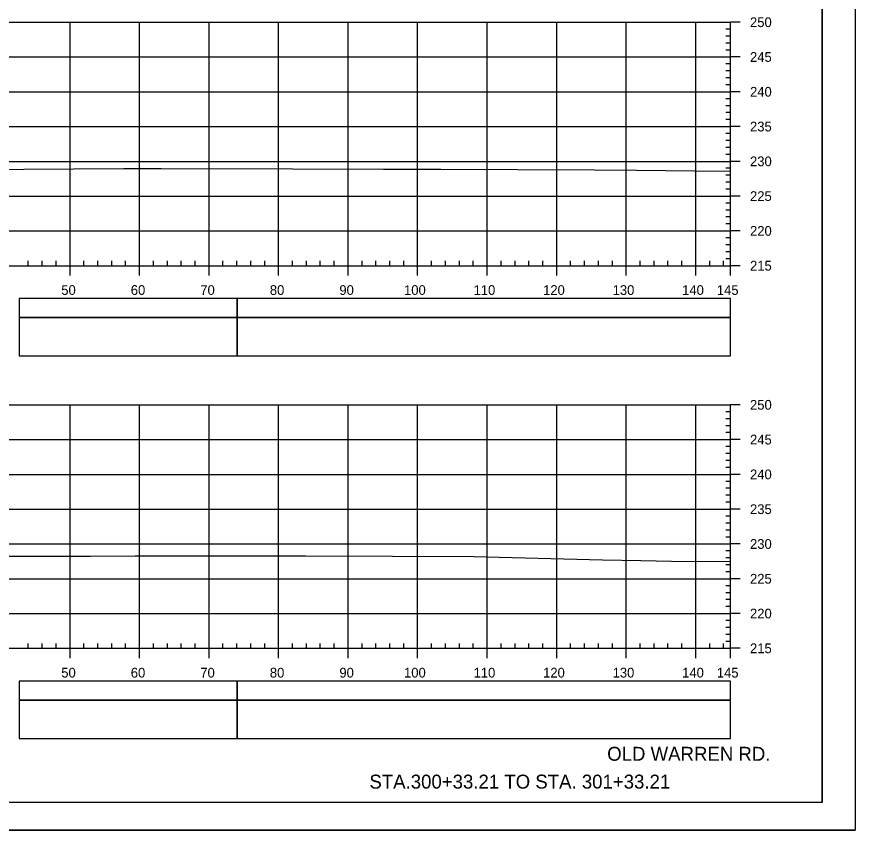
# Model space of a CAD drawing. Extents: x 1386544 to 1388153, y 379785 to 390999.
# Drawn here: x 1386757.2 to 1386877.8, y 384065.3 to 384182.2 of the extents above; entities that cross this region are included whole.
import ezdxf

# ---------------------------------------------------------------- set-up
doc = ezdxf.new("R2010")
doc.units = 0
for name, color, linetype in [('R_Axis', 7, 'Continuous'), ('R_Axis Annot', 7, 'Continuous'), ('R_Border', 7, 'Continuous'), ('R_Draft', 7, 'Continuous'), ('R_Exist Surface', 7, 'Continuous'), ('R_Grid', 7, 'Continuous'), ('R_No Plot', 7, 'Continuous'), ('R_Striping', 7, 'Continuous')]:
    doc.layers.add(name, color=color, linetype=linetype)

msp = doc.modelspace()

# ---------------------------------------------------------------- linework, layer by layer
at = {"layer": 'R_Axis'}
for p, q in [((1386859.87, 384146.41), (1386859.87, 384181.41)), ((1386861.27, 384181.41), (1386859.87, 384181.41)), ((1386859.87, 384180.41), (1386859.17, 384180.41)), ((1386859.87, 384179.41), (1386859.17, 384179.41)), ((1386859.87, 384178.41), (1386859.17, 384178.41)), ((1386859.87, 384177.41), (1386859.17, 384177.41)), ((1386861.27, 384176.41), (1386859.87, 384176.41)), ((1386859.87, 384175.41), (1386859.17, 384175.41)), ((1386859.87, 384174.41), (1386859.17, 384174.41)), ((1386859.87, 384173.41), (1386859.17, 384173.41)), ((1386859.87, 384172.41), (1386859.17, 384172.41)), ((1386861.27, 384171.41), (1386859.87, 384171.41)), ((1386859.87, 384170.41), (1386859.17, 384170.41)), ((1386859.87, 384169.41), (1386859.17, 384169.41)), ((1386859.87, 384168.41), (1386859.17, 384168.41)), ((1386859.87, 384167.41), (1386859.17, 384167.41)), ((1386859.87, 384165.41), (1386859.17, 384165.41)), ((1386861.27, 384166.41), (1386859.87, 384166.41)), ((1386859.87, 384164.41), (1386859.17, 384164.41)), ((1386859.87, 384163.41), (1386859.17, 384163.41)), ((1386859.87, 384162.41), (1386859.17, 384162.41)), ((1386861.27, 384161.41), (1386859.87, 384161.41)), ((1386859.87, 384160.41), (1386859.17, 384160.41)), ((1386859.87, 384159.41), (1386859.17, 384159.41)), ((1386859.87, 384158.41), (1386859.17, 384158.41)), ((1386859.87, 384157.41), (1386859.17, 384157.41)), ((1386861.27, 384156.41), (1386859.87, 384156.41)), ((1386859.87, 384155.41), (1386859.17, 384155.41)), ((1386859.87, 384154.41), (1386859.17, 384154.41)), ((1386859.87, 384153.41), (1386859.17, 384153.41)), ((1386859.87, 384152.41), (1386859.17, 384152.41)), ((1386861.27, 384151.41), (1386859.87, 384151.41)), ((1386859.87, 384150.41), (1386859.17, 384150.41)), ((1386859.87, 384149.41), (1386859.17, 384149.41)), ((1386859.87, 384148.41), (1386859.17, 384148.41)), ((1386859.87, 384147.41), (1386859.17, 384147.41)), ((1386569.87, 384146.41), (1386859.87, 384146.41)), ((1386758.87, 384146.41), (1386758.87, 384147.11)), ((1386760.87, 384146.41), (1386760.87, 384147.11)), ((1386762.87, 384146.41), (1386762.87, 384147.11)), ((1386764.87, 384145.01), (1386764.87, 384146.41)), ((1386766.87, 384146.41), (1386766.87, 384147.11)), ((1386768.87, 384146.41), (1386768.87, 384147.11)), ((1386770.87, 384146.41), (1386770.87, 384147.11)), ((1386772.87, 384146.41), (1386772.87, 384147.11)), ((1386774.87, 384145.01), (1386774.87, 384146.41)), ((1386776.87, 384146.41), (1386776.87, 384147.11)), ((1386778.87, 384146.41), (1386778.87, 384147.11)), ((1386780.87, 384146.41), (1386780.87, 384147.11)), ((1386782.87, 384146.41), (1386782.87, 384147.11)), ((1386784.87, 384145.01), (1386784.87, 384146.41)), ((1386786.87, 384146.41), (1386786.87, 384147.11)), ((1386788.87, 384146.41), (1386788.87, 384147.11)), ((1386790.87, 384146.41), (1386790.87, 384147.11)), ((1386792.87, 384146.41), (1386792.87, 384147.11)), ((1386794.87, 384145.01), (1386794.87, 384146.41)), ((1386796.87, 384146.41), (1386796.87, 384147.11)), ((1386798.87, 384146.41), (1386798.87, 384147.11)), ((1386800.87, 384146.41), (1386800.87, 384147.11)), ((1386802.87, 384146.41), (1386802.87, 384147.11)), ((1386804.87, 384145.01), (1386804.87, 384146.41)), ((1386806.87, 384146.41), (1386806.87, 384147.11)), ((1386808.87, 384146.41), (1386808.87, 384147.11)), ((1386810.87, 384146.41), (1386810.87, 384147.11)), ((1386812.87, 384146.41), (1386812.87, 384147.11)), ((1386814.87, 384145.01), (1386814.87, 384146.41)), ((1386816.87, 384146.41), (1386816.87, 384147.11)), ((1386818.87, 384146.41), (1386818.87, 384147.11)), ((1386820.87, 384146.41), (1386820.87, 384147.11)), ((1386822.87, 384146.41), (1386822.87, 384147.11)), ((1386824.87, 384145.01), (1386824.87, 384146.41)), ((1386826.87, 384146.41), (1386826.87, 384147.11)), ((1386828.87, 384146.41), (1386828.87, 384147.11)), ((1386830.87, 384146.41), (1386830.87, 384147.11)), ((1386832.87, 384146.41), (1386832.87, 384147.11)), ((1386834.87, 384145.01), (1386834.87, 384146.41)), ((1386836.87, 384146.41), (1386836.87, 384147.11)), ((1386838.87, 384146.41), (1386838.87, 384147.11)), ((1386840.87, 384146.41), (1386840.87, 384147.11)), ((1386842.87, 384146.41), (1386842.87, 384147.11)), ((1386844.87, 384145.01), (1386844.87, 384146.41)), ((1386846.87, 384146.41), (1386846.87, 384147.11)), ((1386848.87, 384146.41), (1386848.87, 384147.11)), ((1386850.87, 384146.41), (1386850.87, 384147.11)), ((1386852.87, 384146.41), (1386852.87, 384147.11)), ((1386854.87, 384145.01), (1386854.87, 384146.41)), ((1386856.87, 384146.41), (1386856.87, 384147.11)), ((1386858.87, 384146.41), (1386858.87, 384147.11)), ((1386859.87, 384145.01), (1386859.87, 384146.41)), ((1386861.27, 384146.41), (1386859.87, 384146.41)), ((1386859.87, 384091.41), (1386859.87, 384126.41)), ((1386861.27, 384126.41), (1386859.87, 384126.41)), ((1386859.87, 384125.41), (1386859.17, 384125.41)), ((1386859.87, 384124.41), (1386859.17, 384124.41)), ((1386859.87, 384123.41), (1386859.17, 384123.41)), ((1386859.87, 384122.41), (1386859.17, 384122.41)), ((1386861.27, 384121.41), (1386859.87, 384121.41)), ((1386859.87, 384120.41), (1386859.17, 384120.41)), ((1386859.87, 384119.41), (1386859.17, 384119.41)), ((1386859.87, 384118.41), (1386859.17, 384118.41)), ((1386859.87, 384117.41), (1386859.17, 384117.41)), ((1386861.27, 384116.41), (1386859.87, 384116.41)), ((1386859.87, 384115.41), (1386859.17, 384115.41)), ((1386859.87, 384114.41), (1386859.17, 384114.41)), ((1386859.87, 384113.41), (1386859.17, 384113.41)), ((1386859.87, 384112.41), (1386859.17, 384112.41)), ((1386861.27, 384111.41), (1386859.87, 384111.41)), ((1386859.87, 384110.41), (1386859.17, 384110.41)), ((1386859.87, 384109.41), (1386859.17, 384109.41)), ((1386859.87, 384108.41), (1386859.17, 384108.41)), ((1386859.87, 384107.41), (1386859.17, 384107.41)), ((1386861.27, 384106.41), (1386859.87, 384106.41)), ((1386859.87, 384105.41), (1386859.17, 384105.41)), ((1386859.87, 384104.41), (1386859.17, 384104.41)), ((1386859.87, 384103.41), (1386859.17, 384103.41)), ((1386859.87, 384102.41), (1386859.17, 384102.41)), ((1386859.87, 384100.41), (1386859.17, 384100.41)), ((1386861.27, 384101.41), (1386859.87, 384101.41)), ((1386859.87, 384099.41), (1386859.17, 384099.41)), ((1386859.87, 384098.41), (1386859.17, 384098.41)), ((1386859.87, 384097.41), (1386859.17, 384097.41)), ((1386859.87, 384095.41), (1386859.17, 384095.41)), ((1386861.27, 384096.41), (1386859.87, 384096.41)), ((1386859.87, 384094.41), (1386859.17, 384094.41)), ((1386859.87, 384093.41), (1386859.17, 384093.41)), ((1386758.87, 384091.41), (1386758.87, 384092.11)), ((1386760.87, 384091.41), (1386760.87, 384092.11)), ((1386762.87, 384091.41), (1386762.87, 384092.11)), ((1386766.87, 384091.41), (1386766.87, 384092.11)), ((1386768.87, 384091.41), (1386768.87, 384092.11)), ((1386770.87, 384091.41), (1386770.87, 384092.11)), ((1386772.87, 384091.41), (1386772.87, 384092.11)), ((1386776.87, 384091.41), (1386776.87, 384092.11)), ((1386778.87, 384091.41), (1386778.87, 384092.11)), ((1386780.87, 384091.41), (1386780.87, 384092.11)), ((1386782.87, 384091.41), (1386782.87, 384092.11)), ((1386786.87, 384091.41), (1386786.87, 384092.11)), ((1386788.87, 384091.41), (1386788.87, 384092.11)), ((1386790.87, 384091.41), (1386790.87, 384092.11)), ((1386792.87, 384091.41), (1386792.87, 384092.11)), ((1386796.87, 384091.41), (1386796.87, 384092.11)), ((1386798.87, 384091.41), (1386798.87, 384092.11)), ((1386800.87, 384091.41), (1386800.87, 384092.11)), ((1386802.87, 384091.41), (1386802.87, 384092.11)), ((1386806.87, 384091.41), (1386806.87, 384092.11)), ((1386808.87, 384091.41), (1386808.87, 384092.11)), ((1386810.87, 384091.41), (1386810.87, 384092.11)), ((1386812.87, 384091.41), (1386812.87, 384092.11)), ((1386816.87, 384091.41), (1386816.87, 384092.11)), ((1386818.87, 384091.41), (1386818.87, 384092.11)), ((1386820.87, 384091.41), (1386820.87, 384092.11)), ((1386822.87, 384091.41), (1386822.87, 384092.11)), ((1386826.87, 384091.41), (1386826.87, 384092.11)), ((1386828.87, 384091.41), (1386828.87, 384092.11)), ((1386830.87, 384091.41), (1386830.87, 384092.11)), ((1386832.87, 384091.41), (1386832.87, 384092.11)), ((1386836.87, 384091.41), (1386836.87, 384092.11)), ((1386838.87, 384091.41), (1386838.87, 384092.11)), ((1386840.87, 384091.41), (1386840.87, 384092.11)), ((1386842.87, 384091.41), (1386842.87, 384092.11)), ((1386846.87, 384091.41), (1386846.87, 384092.11)), ((1386848.87, 384091.41), (1386848.87, 384092.11)), ((1386850.87, 384091.41), (1386850.87, 384092.11)), ((1386852.87, 384091.41), (1386852.87, 384092.11)), ((1386856.87, 384091.41), (1386856.87, 384092.11)), ((1386858.87, 384091.41), (1386858.87, 384092.11)), ((1386859.87, 384092.41), (1386859.17, 384092.41)), ((1386569.87, 384091.41), (1386859.87, 384091.41)), ((1386764.87, 384090.01), (1386764.87, 384091.41)), ((1386774.87, 384090.01), (1386774.87, 384091.41)), ((1386784.87, 384090.01), (1386784.87, 384091.41)), ((1386794.87, 384090.01), (1386794.87, 384091.41)), ((1386804.87, 384090.01), (1386804.87, 384091.41)), ((1386814.87, 384090.01), (1386814.87, 384091.41)), ((1386824.87, 384090.01), (1386824.87, 384091.41)), ((1386834.87, 384090.01), (1386834.87, 384091.41)), ((1386844.87, 384090.01), (1386844.87, 384091.41)), ((1386854.87, 384090.01), (1386854.87, 384091.41)), ((1386859.87, 384090.01), (1386859.87, 384091.41)), ((1386861.27, 384091.41), (1386859.87, 384091.41))]:
    msp.add_line(p, q, dxfattribs=at)
at = {"layer": 'R_Axis Annot'}
for points in [[(1386788.89, 384138.97), (1386859.87, 384138.97), (1386859.87, 384141.68), (1386788.89, 384141.68)], [(1386788.89, 384133.44), (1386859.87, 384133.44), (1386859.87, 384138.97), (1386788.89, 384138.97)], [(1386788.89, 384083.97), (1386859.87, 384083.97), (1386859.87, 384086.68), (1386788.89, 384086.68)], [(1386788.89, 384078.44), (1386859.87, 384078.44), (1386859.87, 384083.97), (1386788.89, 384083.97)]]:
    msp.add_lwpolyline(points, close=True, dxfattribs=at)
at = {"layer": 'R_Border'}
for q in [(1386873.05, 384274.71), (1386556.87, 384069.25)]:
    msp.add_line((1386873.05, 384069.25), q, dxfattribs=at)
at = {"layer": 'R_Exist Surface'}
for points in [[(1386751, 384160.24), (1386772.62, 384160.38), (1386774.5, 384160.38), (1386778, 384160.36), (1386796.89, 384160.31), (1386809.97, 384160.27), (1386818.22, 384160.27), (1386840.28, 384160.18), (1386846.32, 384160.15), (1386854.69, 384160.05), (1386859.87, 384159.98)], [(1386750.61, 384104.66), (1386767.82, 384104.68), (1386774.24, 384104.7), (1386777.79, 384104.69), (1386798.74, 384104.71), (1386811.24, 384104.65), (1386822.91, 384104.59), (1386841.44, 384104.12), (1386846.99, 384104.02), (1386851.37, 384103.96), (1386859.87, 384103.91)]]:
    msp.add_lwpolyline(points, dxfattribs=at)
at = {"layer": 'R_Grid'}
for p, q in [((1386569.87, 384181.41), (1386859.87, 384181.41)), ((1386764.87, 384146.41), (1386764.87, 384181.41)), ((1386774.87, 384146.41), (1386774.87, 384181.41)), ((1386784.87, 384146.41), (1386784.87, 384181.41)), ((1386794.87, 384146.41), (1386794.87, 384181.41)), ((1386804.87, 384146.41), (1386804.87, 384181.41)), ((1386814.87, 384146.41), (1386814.87, 384181.41)), ((1386824.87, 384146.41), (1386824.87, 384181.41)), ((1386834.87, 384146.41), (1386834.87, 384181.41)), ((1386844.87, 384146.41), (1386844.87, 384181.41)), ((1386854.87, 384146.41), (1386854.87, 384181.41)), ((1386859.87, 384146.41), (1386859.87, 384181.41)), ((1386569.87, 384176.41), (1386859.87, 384176.41)), ((1386569.87, 384171.41), (1386859.87, 384171.41)), ((1386569.87, 384166.41), (1386859.87, 384166.41)), ((1386569.87, 384161.41), (1386859.87, 384161.41)), ((1386569.87, 384156.41), (1386859.87, 384156.41)), ((1386569.87, 384151.41), (1386859.87, 384151.41)), ((1386569.87, 384146.41), (1386859.87, 384146.41)), ((1386569.87, 384126.41), (1386859.87, 384126.41)), ((1386764.87, 384091.41), (1386764.87, 384126.41)), ((1386774.87, 384091.41), (1386774.87, 384126.41)), ((1386784.87, 384091.41), (1386784.87, 384126.41)), ((1386794.87, 384091.41), (1386794.87, 384126.41)), ((1386804.87, 384091.41), (1386804.87, 384126.41)), ((1386814.87, 384091.41), (1386814.87, 384126.41)), ((1386824.87, 384091.41), (1386824.87, 384126.41)), ((1386834.87, 384091.41), (1386834.87, 384126.41)), ((1386844.87, 384091.41), (1386844.87, 384126.41)), ((1386854.87, 384091.41), (1386854.87, 384126.41)), ((1386859.87, 384091.41), (1386859.87, 384126.41)), ((1386569.87, 384121.41), (1386859.87, 384121.41)), ((1386569.87, 384116.41), (1386859.87, 384116.41)), ((1386569.87, 384111.41), (1386859.87, 384111.41)), ((1386569.87, 384106.41), (1386859.87, 384106.41)), ((1386569.87, 384101.41), (1386859.87, 384101.41)), ((1386569.87, 384096.41), (1386859.87, 384096.41)), ((1386569.87, 384091.41), (1386859.87, 384091.41))]:
    msp.add_line(p, q, dxfattribs=at)
at = {"layer": 'R_No Plot'}
msp.add_line((1386544.47, 384065.27), (1386877.8, 384065.27), dxfattribs=at)
for points in [[(1386544.46, 384278.6), (1386877.8, 384278.6), (1386877.8, 384065.26), (1386544.46, 384065.26)], [(1386790.79, 384274.71), (1386810.41, 384274.71), (1386810.41, 384264.83), (1386826.52, 384264.83), (1386849.72, 384264.83), (1386849.72, 384240.49), (1386873.05, 384240.49), (1386873.05, 384069.25), (1386556.87, 384069.25), (1386556.87, 384274.71)]]:
    msp.add_lwpolyline(points, close=True, dxfattribs=at)
at = {"layer": 'R_Striping'}
for points in [[(1386757.55, 384138.97), (1386788.89, 384138.97), (1386788.89, 384141.68), (1386757.55, 384141.68)], [(1386757.55, 384133.45), (1386788.89, 384133.45), (1386788.89, 384138.97), (1386757.55, 384138.97)], [(1386757.55, 384083.97), (1386788.89, 384083.97), (1386788.89, 384086.68), (1386757.55, 384086.68)], [(1386757.55, 384078.45), (1386788.89, 384078.45), (1386788.89, 384083.97), (1386757.55, 384083.97)]]:
    msp.add_lwpolyline(points, close=True, dxfattribs=at)

# ---------------------------------------------------------------- texts
at = {"layer": 'R_Axis Annot'}
for s, p in [('250', (1386862.67, 384180.71)), ('245', (1386862.67, 384175.71)), ('240', (1386862.67, 384170.71)), ('235', (1386862.67, 384165.71)), ('230', (1386862.67, 384160.71)), ('225', (1386862.67, 384155.71)), ('220', (1386862.67, 384150.71)), ('215', (1386862.67, 384145.71)), ('50', (1386763.61, 384142.21)), ('60', (1386773.61, 384142.21)), ('70', (1386783.61, 384142.21)), ('80', (1386793.61, 384142.21)), ('90', (1386803.61, 384142.21)), ('100', (1386812.91, 384142.21)), ('110', (1386822.91, 384142.21)), ('120', (1386832.91, 384142.21)), ('130', (1386842.91, 384142.21)), ('140', (1386852.91, 384142.21)), ('145', (1386857.9, 384142.21)), ('250', (1386862.67, 384125.71)), ('245', (1386862.67, 384120.71)), ('240', (1386862.67, 384115.71)), ('235', (1386862.67, 384110.71)), ('230', (1386862.67, 384105.71)), ('225', (1386862.67, 384100.71)), ('220', (1386862.67, 384095.71)), ('215', (1386862.67, 384090.71)), ('50', (1386763.61, 384087.21)), ('60', (1386773.61, 384087.21)), ('70', (1386783.61, 384087.21)), ('80', (1386793.61, 384087.21)), ('90', (1386803.61, 384087.21)), ('100', (1386812.91, 384087.21)), ('110', (1386822.91, 384087.21)), ('120', (1386832.91, 384087.21)), ('130', (1386842.91, 384087.21)), ('140', (1386852.91, 384087.21)), ('145', (1386857.9, 384087.21))]:
    msp.add_text(s, height=1.4, dxfattribs=at).set_placement(p)
at = {"layer": 'R_Draft'}
for s, p in [('OLD WARREN RD.', (1386842.13, 384075.25)), ('STA.300+33.21 TO STA. 301+33.21', (1386807.93, 384071.25))]:
    msp.add_text(s, height=2, dxfattribs=at).set_placement(p)

doc.saveas('drawing.dxf')
